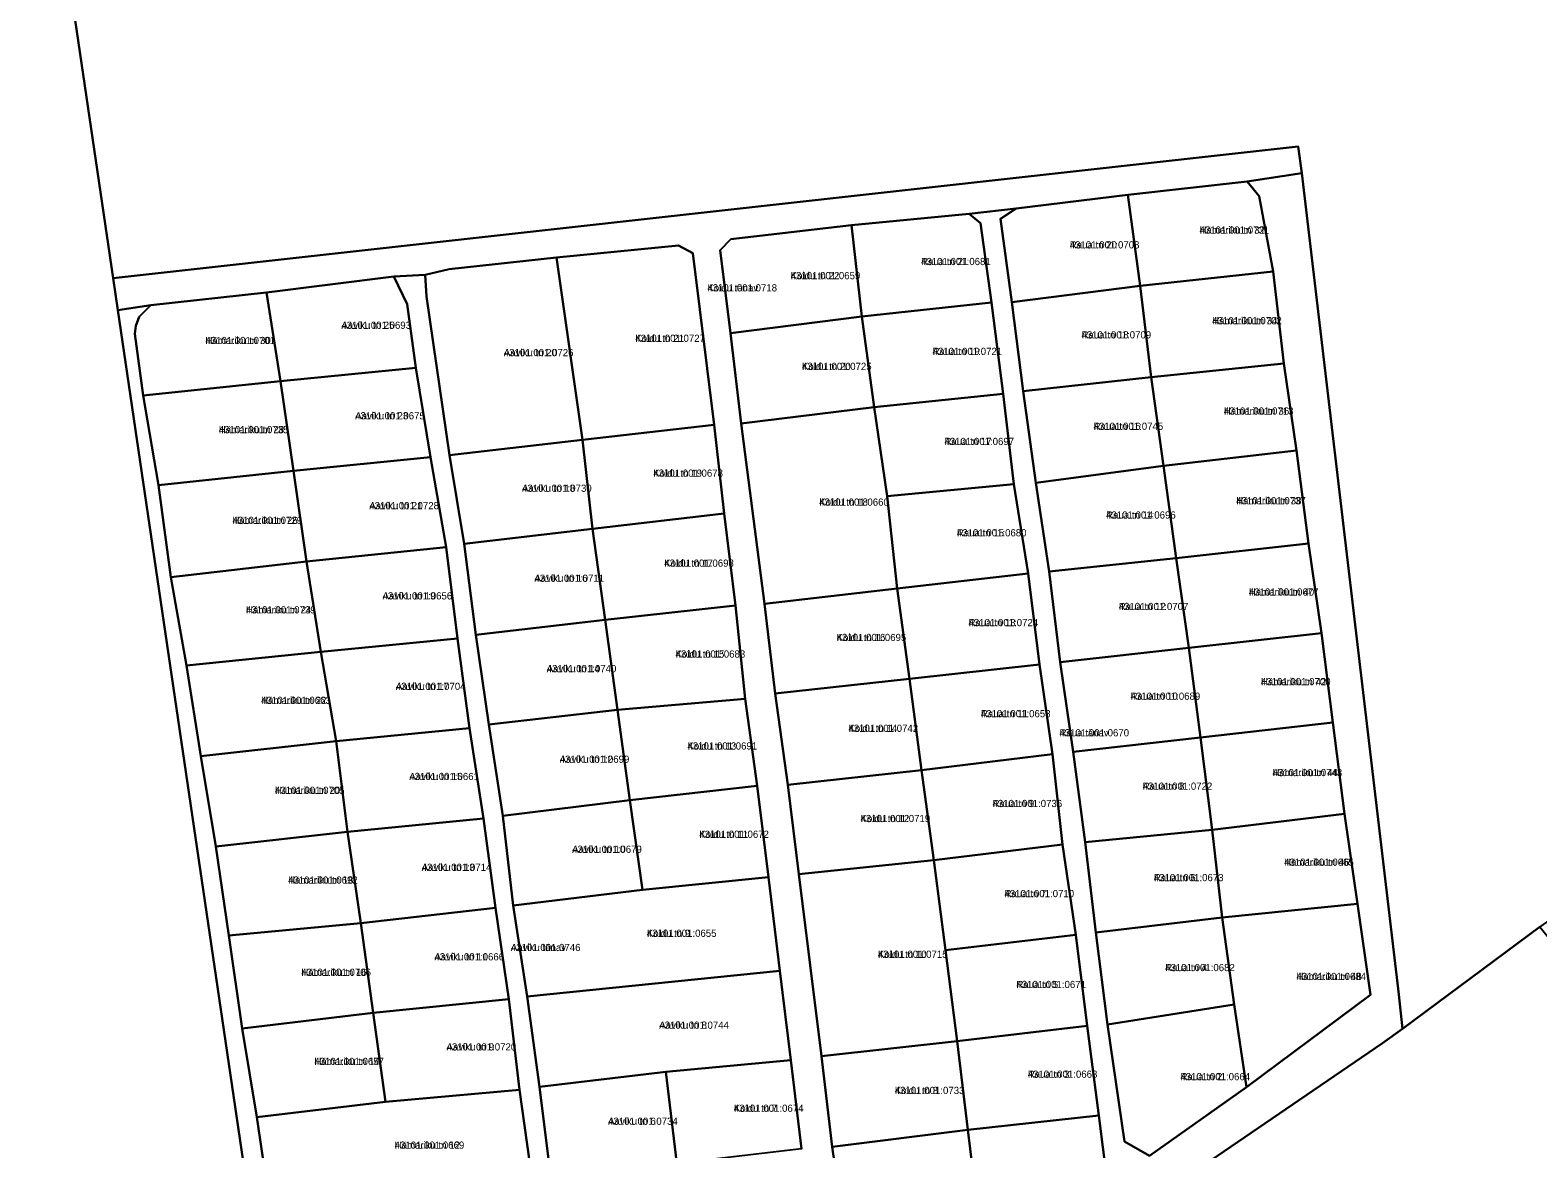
# Model space of a CAD drawing. Extents: x 484607 to 525396, y 6554521 to 6586559.
# Drawn here: x 510881.4 to 511195.3, y 6566323.4 to 6566556.3 of the extents above; entities that cross this region are included whole.
import ezdxf

# ---------------------------------------------------------------- set-up
doc = ezdxf.new("R2010")
doc.units = 0
for name, color, linetype in [('L_AADRESS', 7, 'Continuous'), ('PIIR', 7, 'Continuous'), ('TUNNUS', 7, 'Continuous')]:
    doc.layers.add(name, color=color, linetype=linetype)

msp = doc.modelspace()

# ---------------------------------------------------------------- linework, layer by layer
at = {"layer": 'PIIR'}
for points in [[(510798.29, 6566881.46), (510841.06, 6566895.36), (510898.65, 6566504.69), (510899.62, 6566498.05), (510944.17, 6566195.55), (510944.78, 6566191.44), (510919.04, 6566163.98), (510920.5, 6566161.21), (510972.39, 6566062.69), (510956.12, 6566056.16), (510964.27, 6566035.84), (510980.57, 6566010.49), (510903.8, 6565981.76), (510875.33, 6565935.94), (510855.65, 6566095.24), (510855.17, 6566099.11), (510854.85, 6566103.1), (510794.21, 6566862.32), (510794.75, 6566868.66)], [(511167.15, 6566348.39), (511166.37, 6566355.53), (511146.15, 6566526.53), (511145.41, 6566532.09), (510898.65, 6566504.69), (510841.06, 6566895.36), (511198.95, 6566889.63), (511204.2, 6566890.06), (511203.7, 6566887.49), (511169.8, 6566713.86), (511313.58, 6566665.31), (511318.22, 6566663.75), (511285.26, 6566540.08), (511240.28, 6566412.02), (511240.28, 6566400.91), (511195.72, 6566369.66)], [(511112.52, 6566503.1), (511109.92, 6566522.07), (511134.76, 6566524.84), (511137.27, 6566521.74), (511140.23, 6566506.08)], [(511085.78, 6566499.71), (511083.43, 6566517.07), (511086.67, 6566519.23), (511109.92, 6566522.07), (511112.52, 6566503.1)], [(511054.54, 6566496.71), (511052.43, 6566515.73), (511076.93, 6566518.12), (511079.25, 6566516.12), (511081.54, 6566499.6)], [(511027.23, 6566493.22), (511025.04, 6566510.53), (511027.27, 6566512.83), (511052.43, 6566515.73), (511054.54, 6566496.71)], [(510963.9, 6566500.86), (510963.64, 6566505.39), (510968.63, 6566506.56), (510990.98, 6566508.99), (510996.4, 6566471.01), (510968.73, 6566467.83)], [(510996.4, 6566471.01), (510990.98, 6566508.99), (511016.42, 6566511.47), (511019.34, 6566509.93), (511023.81, 6566474.17)], [(511114.83, 6566484.12), (511112.52, 6566503.1), (511140.23, 6566506.08), (511142.44, 6566486.95)], [(510933.5, 6566483.23), (510930.62, 6566501.69), (510957.11, 6566505.07), (510959.89, 6566499.27), (510961.68, 6566486.01)], [(511088.13, 6566481.2), (511085.78, 6566499.71), (511112.52, 6566503.1), (511114.83, 6566484.12)], [(510904.08, 6566496.67), (510906.49, 6566499.08), (510930.62, 6566501.69), (510933.5, 6566483.23), (510904.89, 6566480.27), (510903.15, 6566493.14), (510903.37, 6566494.81)], [(511057.12, 6566477.81), (511054.54, 6566496.71), (511081.54, 6566499.6), (511083.97, 6566480.6)], [(511029.46, 6566474.47), (511027.23, 6566493.22), (511054.54, 6566496.71), (511057.12, 6566477.81)], [(511117.39, 6566465.62), (511114.83, 6566484.12), (511142.44, 6566486.95), (511145.04, 6566468.83)], [(510936.24, 6566464.59), (510933.5, 6566483.23), (510961.68, 6566486.01), (510964.76, 6566467.46)], [(511090.82, 6566462.09), (511088.13, 6566481.2), (511114.83, 6566484.12), (511117.39, 6566465.62)], [(510908.1, 6566461.61), (510904.89, 6566480.27), (510933.5, 6566483.23), (510936.24, 6566464.59)], [(511059.83, 6566459.31), (511057.12, 6566477.81), (511083.97, 6566480.6), (511086.24, 6566461.79)], [(511034.29, 6566436.93), (511029.46, 6566474.47), (511057.12, 6566477.81), (511059.83, 6566459.31), (511061.9, 6566440.09)], [(510998.51, 6566452.54), (510996.4, 6566471.01), (511023.81, 6566474.17), (511025.86, 6566455.69)], [(510971.76, 6566449.42), (510968.73, 6566467.83), (510996.4, 6566471.01), (510998.51, 6566452.54)], [(511120.04, 6566446.42), (511117.39, 6566465.62), (511145.04, 6566468.83), (511147.56, 6566449.46)], [(510938.92, 6566445.71), (510936.24, 6566464.59), (510964.76, 6566467.46), (510968, 6566448.7)], [(511093.58, 6566443.66), (511090.82, 6566462.09), (511117.39, 6566465.62), (511120.04, 6566446.42)], [(510910.67, 6566442.47), (510908.1, 6566461.61), (510936.24, 6566464.59), (510938.92, 6566445.71)], [(511061.9, 6566440.09), (511059.83, 6566459.31), (511086.24, 6566461.79), (511089.19, 6566443.21)], [(511001.11, 6566433.55), (510998.51, 6566452.54), (511025.86, 6566455.69), (511028.22, 6566436.58)], [(510974.16, 6566430.41), (510971.76, 6566449.42), (510998.51, 6566452.54), (511001.11, 6566433.55)], [(511122.65, 6566427.76), (511120.04, 6566446.42), (511147.56, 6566449.46), (511150.28, 6566430.78)], [(510941.9, 6566426.92), (510938.92, 6566445.71), (510968, 6566448.7), (510970.36, 6566429.67)], [(511095.83, 6566424.78), (511093.58, 6566443.66), (511120.04, 6566446.42), (511122.65, 6566427.76)], [(510913.92, 6566424.09), (510910.67, 6566442.47), (510938.92, 6566445.71), (510941.9, 6566426.92)], [(511064.48, 6566421.27), (511061.9, 6566440.09), (511089.19, 6566443.21), (511091.55, 6566424.29)], [(511036.53, 6566418.22), (511034.29, 6566436.93), (511061.9, 6566440.09), (511064.48, 6566421.27)], [(511003.67, 6566414.82), (511001.11, 6566433.55), (511028.22, 6566436.58), (511030.29, 6566417.11)], [(510976.9, 6566411.77), (510974.16, 6566430.41), (511001.11, 6566433.55), (511003.67, 6566414.82)], [(511125.11, 6566409.09), (511122.65, 6566427.76), (511150.28, 6566430.78), (511152.62, 6566412.21)], [(510945.13, 6566408.27), (510941.9, 6566426.92), (510970.36, 6566429.67), (510972.89, 6566411)], [(511098.54, 6566406.07), (511095.83, 6566424.78), (511122.65, 6566427.76), (511125.11, 6566409.09)], [(510916.9, 6566405.18), (510913.92, 6566424.09), (510941.9, 6566426.92), (510945.13, 6566408.27)], [(511066.99, 6566402.26), (511064.48, 6566421.27), (511091.55, 6566424.29), (511094.28, 6566405.61)], [(511039.14, 6566399.2), (511036.53, 6566418.22), (511064.48, 6566421.27), (511066.99, 6566402.26)], [(510979.84, 6566392.78), (510976.9, 6566411.77), (511003.67, 6566414.82), (511006.22, 6566396)], [(511006.22, 6566396), (511003.67, 6566414.82), (511030.29, 6566417.11), (511032.77, 6566398.98)], [(511127.5, 6566389.83), (511125.11, 6566409.09), (511152.62, 6566412.21), (511155.03, 6566393.16)], [(510920.06, 6566386.37), (510916.9, 6566405.18), (510945.13, 6566408.27), (510947.44, 6566389.41)], [(510947.44, 6566389.41), (510945.13, 6566408.27), (510972.89, 6566411), (510975.76, 6566392.18)], [(511101.04, 6566387.28), (511098.54, 6566406.07), (511125.11, 6566409.09), (511127.5, 6566389.83)], [(511069.58, 6566383.56), (511066.99, 6566402.26), (511094.28, 6566405.61), (511096.35, 6566386.82)], [(511041.44, 6566380.64), (511039.14, 6566399.2), (511066.99, 6566402.26), (511069.58, 6566383.56)], [(511008.86, 6566377.35), (511006.22, 6566396), (511032.77, 6566398.98), (511035.13, 6566380)], [(510981.98, 6566374.11), (510979.84, 6566392.78), (511006.22, 6566396), (511008.86, 6566377.35)], [(511129.61, 6566371.56), (511127.5, 6566389.83), (511155.03, 6566393.16), (511157.79, 6566374.41)], [(510922.77, 6566367.86), (510920.06, 6566386.37), (510947.44, 6566389.41), (510950.21, 6566370.39)], [(510950.21, 6566370.39), (510947.44, 6566389.41), (510975.76, 6566392.18), (510978.26, 6566373.6)], [(511103.26, 6566368.46), (511101.04, 6566387.28), (511127.5, 6566389.83), (511129.61, 6566371.56)], [(511071.95, 6566364.82), (511069.58, 6566383.56), (511096.35, 6566386.82), (511099.12, 6566367.96)], [(511046.19, 6566342.75), (511041.44, 6566380.64), (511069.58, 6566383.56), (511071.95, 6566364.82), (511074.38, 6566345.83)], [(510984.86, 6566355.12), (510981.98, 6566374.11), (511008.86, 6566377.35), (511035.13, 6566380), (511037.47, 6566360.52)], [(511132.11, 6566353.48), (511129.61, 6566371.56), (511157.79, 6566374.41), (511160.48, 6566355.52), (511134.64, 6566336.25)], [(510952.8, 6566351.72), (510950.21, 6566370.39), (510978.26, 6566373.6), (510981.03, 6566354.61)], [(511105.7, 6566349.28), (511103.26, 6566368.46), (511129.61, 6566371.56), (511132.11, 6566353.48)], [(510925.54, 6566348.47), (510922.77, 6566367.86), (510950.21, 6566370.39), (510952.8, 6566351.72)], [(511167.15, 6566348.39), (511195.72, 6566369.66), (511229.31, 6566328.43), (511197.85, 6566289.25), (511235.29, 6566228.71), (511213.97, 6566194.63), (511250.38, 6566142.85), (511256.39, 6566114.86), (511216.4, 6566103.03), (511185.24, 6566094.86), (511173.08, 6566091.4), (511165.87, 6566097.92), (511159.18, 6566104.64), (511153.91, 6566112.9), (511145.54, 6566128.22), (511105.24, 6566193.93), (511096.69, 6566209.97), (511080.89, 6566243.45), (511069.79, 6566262.38), (511061.46, 6566274.23), (511088.35, 6566293.42), (511127.12, 6566320.93), (511162.99, 6566345.41)], [(511074.38, 6566345.83), (511071.95, 6566364.82), (511099.12, 6566367.96), (511101.46, 6566349.03)], [(510987.42, 6566336.34), (510984.86, 6566355.12), (511037.47, 6566360.52), (511039.81, 6566341.91), (511013.75, 6566339.47)], [(510928.61, 6566330.04), (510925.54, 6566348.47), (510952.8, 6566351.72), (510955.38, 6566333.19)], [(510955.38, 6566333.19), (510952.8, 6566351.72), (510981.03, 6566354.61), (510983.27, 6566335.71)], [(511109.24, 6566324.92), (511105.7, 6566349.28), (511132.11, 6566353.48), (511134.64, 6566336.25), (511114.47, 6566321.95)], [(511076.65, 6566327.41), (511074.38, 6566345.83), (511101.46, 6566349.03), (511103.93, 6566330.36)], [(511048.39, 6566323.85), (511046.19, 6566342.75), (511074.38, 6566345.83), (511076.65, 6566327.41)], [(510989.77, 6566317.4), (510987.42, 6566336.34), (511013.75, 6566339.47), (511016.02, 6566320.36)], [(511016.02, 6566320.36), (511013.75, 6566339.47), (511039.81, 6566341.91), (511041.99, 6566323.42)], [(510931.35, 6566311.19), (510928.61, 6566330.04), (510955.38, 6566333.19), (510983.27, 6566335.71), (510985.9, 6566316.93), (510958.13, 6566314.42)], [(511078.92, 6566308.7), (511076.65, 6566327.41), (511103.93, 6566330.36), (511105.55, 6566317.2), (511104.3, 6566314.95), (511081.13, 6566298.06)], [(511051.14, 6566304.74), (511048.39, 6566323.85), (511076.65, 6566327.41), (511078.92, 6566308.7)]]:
    msp.add_lwpolyline(points, close=True, dxfattribs=at)
for points in [[(511041.99, 6566323.42), (511039.81, 6566341.91), (511037.47, 6566360.52), (511035.13, 6566380), (511032.77, 6566398.98), (511030.29, 6566417.11), (511028.22, 6566436.58), (511025.86, 6566455.69), (511023.81, 6566474.17), (511019.34, 6566509.93), (511016.42, 6566511.47), (510990.98, 6566508.99), (510968.63, 6566506.56), (510963.64, 6566505.39), (510957.11, 6566505.07), (510930.62, 6566501.69), (510906.49, 6566499.08), (510899.62, 6566498.05), (510898.65, 6566504.69), (511145.41, 6566532.09), (511146.15, 6566526.53), (511134.76, 6566524.84), (511109.92, 6566522.07), (511086.67, 6566519.23), (511076.93, 6566518.12), (511052.43, 6566515.73), (511027.27, 6566512.83), (511025.04, 6566510.53), (511027.23, 6566493.22), (511029.46, 6566474.47), (511034.29, 6566436.93), (511036.53, 6566418.22), (511039.14, 6566399.2), (511041.44, 6566380.64), (511046.19, 6566342.75), (511048.39, 6566323.85), (511051.14, 6566304.74)], [(511114.47, 6566321.95), (511134.64, 6566336.25), (511160.48, 6566355.52), (511157.79, 6566374.41), (511155.03, 6566393.16), (511152.62, 6566412.21), (511150.28, 6566430.78), (511147.56, 6566449.46), (511145.04, 6566468.83), (511142.44, 6566486.95), (511140.23, 6566506.08), (511137.27, 6566521.74), (511134.76, 6566524.84), (511146.15, 6566526.53), (511166.37, 6566355.53), (511167.15, 6566348.39), (511162.99, 6566345.41), (511127.12, 6566320.93)], [(511105.55, 6566317.2), (511103.93, 6566330.36), (511101.46, 6566349.03), (511099.12, 6566367.96), (511096.35, 6566386.82), (511094.28, 6566405.61), (511091.55, 6566424.29), (511089.19, 6566443.21), (511086.24, 6566461.79), (511083.97, 6566480.6), (511081.54, 6566499.6), (511079.25, 6566516.12), (511076.93, 6566518.12), (511086.67, 6566519.23), (511083.43, 6566517.07), (511085.78, 6566499.71), (511088.13, 6566481.2), (511090.82, 6566462.09), (511093.58, 6566443.66), (511095.83, 6566424.78), (511098.54, 6566406.07), (511101.04, 6566387.28), (511103.26, 6566368.46), (511105.7, 6566349.28), (511109.24, 6566324.92), (511114.47, 6566321.95)], [(510985.9, 6566316.93), (510983.27, 6566335.71), (510981.03, 6566354.61), (510978.26, 6566373.6), (510975.76, 6566392.18), (510972.89, 6566411), (510970.36, 6566429.67), (510968, 6566448.7), (510964.76, 6566467.46), (510961.68, 6566486.01), (510959.89, 6566499.27), (510957.11, 6566505.07), (510963.64, 6566505.39), (510963.9, 6566500.86), (510968.73, 6566467.83), (510971.76, 6566449.42), (510974.16, 6566430.41), (510976.9, 6566411.77), (510979.84, 6566392.78), (510981.98, 6566374.11), (510984.86, 6566355.12), (510987.42, 6566336.34), (510989.77, 6566317.4)], [(510944.17, 6566195.55), (510899.62, 6566498.05), (510906.49, 6566499.08), (510904.08, 6566496.67), (510903.37, 6566494.81), (510903.15, 6566493.14), (510904.89, 6566480.27), (510908.1, 6566461.61), (510910.67, 6566442.47), (510913.92, 6566424.09), (510916.9, 6566405.18), (510920.06, 6566386.37), (510922.77, 6566367.86), (510925.54, 6566348.47), (510928.61, 6566330.04), (510931.35, 6566311.19)]]:
    msp.add_lwpolyline(points, dxfattribs=at)

# ---------------------------------------------------------------- texts
at = {"layer": 'L_AADRESS'}
for s, p in [('Hämariku tn 32', (511124.88, 6566513.97)), ('Raua tn 20', (511097.86, 6566510.89)), ('Raua tn 21', (511066.9, 6566507.42)), ('Koidu tn 22', (511039.74, 6566504.48)), ('Koidu tänav', (511022.4, 6566501.94)), ('Hämariku tn 34', (511127.5, 6566495.1)), ('Aaviku tn 25', (510946.19, 6566494.15)), ('Koidu tn 21', (511007.39, 6566491.43)), ('Raua tn 18', (511100.3, 6566492.15)), ('Hämariku tn 30', (510917.87, 6566490.98)), ('Aaviku tn 20', (510980.02, 6566488.46)), ('Raua tn 19', (511069.28, 6566488.71)), ('Koidu tn 20', (511042.1, 6566485.59)), ('Hämariku tn 36', (511129.94, 6566476.29)), ('Aaviku tn 23', (510949.06, 6566475.3)), ('Raua tn 16', (511102.81, 6566473.11)), ('Hämariku tn 28', (510920.66, 6566472.42)), ('Raua tn 17', (511071.76, 6566469.96)), ('Koidu tn 19', (511011.14, 6566463.36)), ('Aaviku tn 18', (510983.81, 6566460.22)), ('Koidu tn 18', (511045.68, 6566457.33)), ('Hämariku tn 38', (511132.5, 6566457.62)), ('Aaviku tn 21', (510952.01, 6566456.59)), ('Raua tn 14', (511105.42, 6566454.64)), ('Hämariku tn 26', (510923.5, 6566453.53)), ('Raua tn 15', (511074.35, 6566450.94)), ('Koidu tn 17', (511013.41, 6566444.62)), ('Aaviku tn 16', (510986.39, 6566441.48)), ('Hämariku tn 40', (511135.14, 6566438.61)), ('Hämariku tn 24', (510926.32, 6566434.9)), ('Aaviku tn 19', (510954.76, 6566437.81)), ('Raua tn 12', (511108.05, 6566435.6)), ('Raua tn 13', (511076.77, 6566432.24)), ('Koidu tn 16', (511049.31, 6566429.15)), ('Koidu tn 15', (511015.78, 6566425.7)), ('Aaviku tn 14', (510988.95, 6566422.66)), ('Hämariku tn 42', (511137.66, 6566419.94)), ('Hämariku tn 22', (510929.48, 6566416.05)), ('Aaviku tn 17', (510957.54, 6566418.97)), ('Raua tn 10', (511110.52, 6566416.92)), ('Raua tn 11', (511079.35, 6566413.28)), ('Koidu tn 14', (511051.78, 6566410.24)), ('Raua tänav', (511095.7, 6566409.3)), ('Aaviku tn 12', (510991.65, 6566403.8)), ('Koidu tn 13', (511018.26, 6566406.55)), ('Hämariku tn 44', (511140.07, 6566401.02)), ('Hämariku tn 20', (510932.35, 6566397.32)), ('Aaviku tn 15', (510960.33, 6566400.21)), ('Raua tn 8', (511113.03, 6566398.19)), ('Raua tn 9', (511081.77, 6566394.58)), ('Koidu tn 12', (511054.29, 6566391.45)), ('Koidu tn 11', (511020.72, 6566388.17)), ('Aaviku tn 10', (510994.25, 6566385.05)), ('Hämariku tn 46', (511142.49, 6566382.36)), ('Hämariku tn 18', (510935.1, 6566378.63)), ('Aaviku tn 13', (510962.92, 6566381.29)), ('Raua tn 6', (511115.37, 6566379.15)), ('Raua tn 7', (511084.26, 6566375.82)), ('Koidu tn 9', (511009.8, 6566367.56)), ('Aaviku tn 11', (510965.57, 6566362.66)), ('Aaviku tänav', (510981.48, 6566364.6)), ('Koidu tn 10', (511057.91, 6566363.19)), ('Raua tn 4', (511117.72, 6566360.42)), ('Hämariku tn 16', (510937.85, 6566359.43)), ('Raua tn 5', (511086.73, 6566356.9)), ('Hämariku tn 48', (511145.04, 6566358.57)), ('Aaviku tn 8', (511012.38, 6566348.43)), ('Aaviku tn 9', (510968.09, 6566343.9)), ('Hämariku tn 14', (510940.56, 6566340.88)), ('Raua tn 3', (511089.1, 6566338.22)), ('Raua tn 2', (511120.9, 6566337.71)), ('Koidu tn 8', (511061.42, 6566334.84)), ('Aaviku tn 6', (511001.73, 6566328.43)), ('Koidu tn 7', (511027.91, 6566331.13)), ('Hämariku tn 12', (510957.28, 6566323.45))]:
    msp.add_text(s, height=1.5, dxfattribs=at).set_placement(p)
at = {"layer": 'TUNNUS'}
for s, p in [('43101:001:0731', (511124.88, 6566513.97)), ('43101:001:0708', (511097.86, 6566510.89)), ('43101:001:0681', (511066.9, 6566507.42)), ('43101:001:0659', (511039.74, 6566504.48)), ('43101:001:0718', (511022.4, 6566501.94)), ('43101:001:0702', (511127.5, 6566495.1)), ('43101:001:0693', (510946.19, 6566494.15)), ('43101:001:0727', (511007.39, 6566491.43)), ('43101:001:0709', (511100.3, 6566492.15)), ('43101:001:0701', (510917.87, 6566490.98)), ('43101:001:0726', (510980.02, 6566488.46)), ('43101:001:0721', (511069.28, 6566488.71)), ('43101:001:0725', (511042.1, 6566485.59)), ('43101:001:0713', (511129.94, 6566476.29)), ('43101:001:0675', (510949.06, 6566475.3)), ('43101:001:0745', (511102.81, 6566473.11)), ('43101:001:0735', (510920.66, 6566472.42)), ('43101:001:0697', (511071.76, 6566469.96)), ('43101:001:0678', (511011.14, 6566463.36)), ('43101:001:0730', (510983.81, 6566460.22)), ('43101:001:0660', (511045.68, 6566457.33)), ('43101:001:0737', (511132.5, 6566457.62)), ('43101:001:0728', (510952.01, 6566456.59)), ('43101:001:0696', (511105.42, 6566454.64)), ('43101:001:0729', (510923.5, 6566453.53)), ('43101:001:0680', (511074.35, 6566450.94)), ('43101:001:0698', (511013.41, 6566444.62)), ('43101:001:0711', (510986.39, 6566441.48)), ('43101:001:0677', (511135.14, 6566438.61)), ('43101:001:0656', (510954.76, 6566437.81)), ('43101:001:0707', (511108.05, 6566435.6)), ('43101:001:0739', (510926.32, 6566434.9)), ('43101:001:0724', (511076.77, 6566432.24)), ('43101:001:0695', (511049.31, 6566429.15)), ('43101:001:0683', (511015.78, 6566425.7)), ('43101:001:0740', (510988.95, 6566422.66)), ('43101:001:0700', (511137.66, 6566419.94)), ('43101:001:0704', (510957.54, 6566418.97)), ('43101:001:0689', (511110.52, 6566416.92)), ('43101:001:0663', (510929.48, 6566416.05)), ('43101:001:0658', (511079.35, 6566413.28)), ('43101:001:0742', (511051.78, 6566410.24)), ('43101:001:0670', (511095.7, 6566409.3)), ('43101:001:0699', (510991.65, 6566403.8)), ('43101:001:0691', (511018.26, 6566406.55)), ('43101:001:0743', (511140.07, 6566401.02)), ('43101:001:0705', (510932.35, 6566397.32)), ('43101:001:0661', (510960.33, 6566400.21)), ('43101:001:0722', (511113.03, 6566398.19)), ('43101:001:0736', (511081.77, 6566394.58)), ('43101:001:0719', (511054.29, 6566391.45)), ('43101:001:0672', (511020.72, 6566388.17)), ('43101:001:0679', (510994.25, 6566385.05)), ('43101:001:0665', (511142.49, 6566382.36)), ('43101:001:0692', (510935.1, 6566378.63)), ('43101:001:0714', (510962.92, 6566381.29)), ('43101:001:0673', (511115.37, 6566379.15)), ('43101:001:0710', (511084.26, 6566375.82)), ('43101:001:0655', (511009.8, 6566367.56)), ('43101:001:0746', (510981.48, 6566364.6)), ('43101:001:0715', (511057.91, 6566363.19)), ('43101:001:0666', (510965.57, 6566362.66)), ('43101:001:0682', (511117.72, 6566360.42)), ('43101:001:0706', (510937.85, 6566359.43)), ('43101:001:0671', (511086.73, 6566356.9)), ('43101:001:0684', (511145.04, 6566358.57)), ('43101:001:0744', (511012.38, 6566348.43)), ('43101:001:0720', (510968.09, 6566343.9)), ('43101:001:0657', (510940.56, 6566340.88)), ('43101:001:0668', (511089.1, 6566338.22)), ('43101:001:0664', (511120.9, 6566337.71)), ('43101:001:0733', (511061.42, 6566334.84)), ('43101:001:0734', (511001.73, 6566328.43)), ('43101:001:0674', (511027.91, 6566331.13)), ('43101:001:0669', (510957.28, 6566323.45))]:
    msp.add_text(s, height=1.5, dxfattribs=at).set_placement(p)

doc.saveas('drawing.dxf')
